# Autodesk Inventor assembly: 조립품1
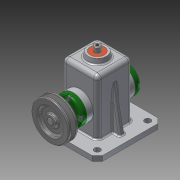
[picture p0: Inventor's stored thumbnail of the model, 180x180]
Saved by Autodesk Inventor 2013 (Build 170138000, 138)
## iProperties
Created: 2016-02
Part Number: 조립품1
Document SubType Name: Assembly
Designer: dgall
Author: dgall
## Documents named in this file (16)
- C:\Users\dgall\Desktop\460211V1008\조립품1.iam
- C:\Users\dgall\Desktop\460211V1008\V벨트풀리.ipt
- C:\Users\dgall\Desktop\460211V1008\고정핀 1.2 x 10.ipt
- C:\Users\dgall\Desktop\460211V1008\뒤커버.ipt
- C:\Users\dgall\Desktop\460211V1008\링크.ipt
- C:\Users\dgall\Desktop\460211V1008\멈춤나사 M3x8.ipt
- C:\Users\dgall\Desktop\460211V1008\베어링 12 x 32 x 10.ipt
- C:\Users\dgall\Desktop\460211V1008\볼트 M4 x 12.ipt
- C:\Users\dgall\Desktop\460211V1008\부시.ipt
- C:\Users\dgall\Desktop\460211V1008\부품1.ipt
- C:\Users\dgall\Desktop\460211V1008\슬라이드.ipt
- C:\Users\dgall\Desktop\460211V1008\앞커버.ipt
- C:\Users\dgall\Desktop\460211V1008\오일실 12 25 7.ipt
- C:\Users\dgall\Desktop\460211V1008\키 4 x 4 x 10.ipt
- C:\Users\dgall\Desktop\460211V1008\편심축.ipt
- C:\Users\dgall\Desktop\460211V1008\핀 5 x 18.ipt
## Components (11 placed, 4 different names)
1. V벨트풀리:1
2. 고정핀 1.2 x 10:1
3. ISO 4762 M4 x 12:1
4. 핀 5 x 18:1
5. ISO 4762 M4 x 12:2
6. ISO 4762 M4 x 12:3
7. ISO 4762 M4 x 12:4
8. ISO 4762 M4 x 12:5
9. ISO 4762 M4 x 12:6
10. ISO 4762 M4 x 12:7
11. ISO 4762 M4 x 12:8
